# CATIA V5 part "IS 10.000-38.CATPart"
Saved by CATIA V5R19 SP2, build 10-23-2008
Part number: IS 10.000-38
Bounding box of the stored display mesh (mm): x -97.324 to 97.324, y -97.5 to 97.5, z 0 to 236
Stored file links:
  C:\Users\Bora\Desktop\3D Katı model\IS serisi\IS 10.000\IS 10.000-38.CATPart
  C:\Program Files\Dassault Systemes\B19\intel_a\reffiles\standard\MetricThickPitch.txt
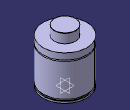
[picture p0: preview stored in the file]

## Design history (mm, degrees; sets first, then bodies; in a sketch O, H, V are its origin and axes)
Body1 (main body)
  Sketch1 on yz-plane, origin (0, 0, 0), H (0, 1, 0), V (0, 0, 1)
    point P1 (97.5, 167)
    point P2 (97.5, 162)
    point P5 (47.5, 235)
    point P7 (47.5, 235)
    point P12 (97.5, 162)
    point P13 (97.5, 167)
    arc A1 centre (97.5, 164.5) radius 2.5 from (97.5, 167) to (97.5, 162) ccw
    line L1 (97.5, 0) -> (97.5, 8)
    line L2 (47.5, 235) -> (47.5, 195)
    arc A2 centre (46.5, 235) radius 1 from (47.5, 235) to (46.5, 236) ccw
    line L3 (93.5, 16) -> (93.5, 8)
    line L4 (97.5, 16) -> (97.5, 162)
    line L5 (97.5, 167) -> (97.5, 195)
    line L6 (46.5, 236) -> (0, 236)
    point P15 (0, 236)
    line L7 (47.5, 195) -> (97.5, 195)
    line L8 (93.5, 16) -> (97.5, 16)
    line L9 (93.5, 8) -> (97.5, 8)
    line L10 (97.5, 0) -> (0, 0)
    tangency: L6 A2
    coincidence: P15 V, P1 P13, P2 P12, P5 P7
    horizontal: L7 H, L8 H, L9 H, L10 H
  Shaft1: profile Sketch1, axis Sketch1.V, angle 360
  Sketch2 on face of Shaft1 from Sketch1.L10, origin (0, 0, 0), H (1, 0, 0), V (0, -1, 0)
    point P1 (60, 0)
    distance P1 V = 60
  Hole1: placed by Sketch2, at (60, 0, 0) direction (0, 0, 1), diameter 10.106, depth 16, threaded "M12", thread diameter 12, thread depth 16, pitch 1.75
  CircPattern1: of Hole1, instances 4, angular step 90, axis from xy-plane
